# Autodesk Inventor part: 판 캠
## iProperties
Company: 한국ATC센터
Created: 2014-07
Part Number: 판 캠
Document SubType Name: 모델링
Designer: KYOUNG IL JANG
변환 표준: STEP AP214IS
파일 이름: C:\Users\SeoGD\Desktop\?쒗뿕\??stp
전처리기: Build: 253, Release: 2010 SP1 - Date: Wed 07/29/2009
전송 단위: 밀리미터
불확실성: 0.01
Author: KYOUNG IL JANG
